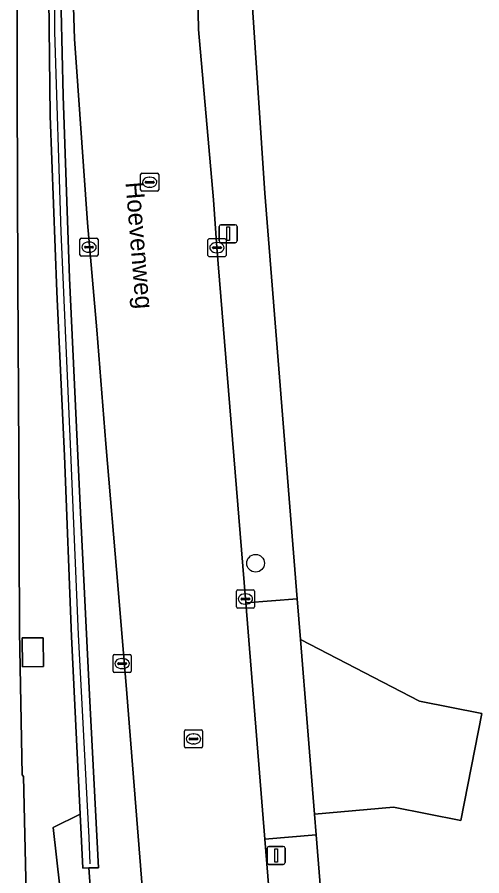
# Model space of a CAD drawing. Extents: x 157692 to 159674, y 381452 to 383291.
# Drawn here: x 157862.74 to 157888.49, y 382049.29 to 382096.87 of the extents above; entities that cross this region are included whole.
import ezdxf

# ---------------------------------------------------------------- set-up
doc = ezdxf.new("R2010")
doc.units = 0
for name, color, linetype in [('IMGEO_Berm_groen', 7, 'Continuous'), ('IMGEO_Boom', 7, 'Continuous'), ('IMGEO_Damwand', 7, 'Continuous'), ('IMGEO_Erf', 7, 'Continuous'), ('IMGEO_Grasland_overig', 7, 'Continuous'), ('IMGEO_Kolk', 7, 'Continuous'), ('IMGEO_Lichtmast', 7, 'Continuous'), ('IMGEO_Muur', 7, 'Continuous'), ('IMGEO_Openbare_ruimte_label', 7, 'Continuous'), ('IMGEO_Rijbaan_autoweg', 7, 'Continuous'), ('IMGEO_Rijbaan_lokaal_open', 7, 'Continuous'), ('IMGEO_Rioolput', 7, 'Continuous'), ('IMGEO_Terreindeel_gesloten', 7, 'Continuous'), ('IMGEO_Voetpad_open', 7, 'Continuous')]:
    doc.layers.add(name, color=color, linetype=linetype)

msp = doc.modelspace()

# ---------------------------------------------------------------- linework, layer by layer
at = {"layer": 'IMGEO_Berm_groen'}
for points in [[(157865.425, 382160.91), (157865.05, 382154.363), (157864.474, 382147.952), (157864.058, 382142.231), (157865.186, 382142.176), (157865.108, 382140.578), (157863.948, 382140.634), (157863.712, 382136.719), (157863.198, 382126.221), (157862.886, 382118.229), (157862.796, 382114.688), (157862.791, 382104.04), (157862.748, 382099.529), (157862.74, 382092.835), (157862.768, 382082.253), (157862.839, 382072.603), (157862.865, 382062.831), (157863.011, 382054.891), (157863.082, 382054.797), (157863.405, 382041.04)], [(157871.576, 382023.267), (157870.986, 382031.847), (157870.47, 382038.411), (157869.622, 382049.165), (157868.821, 382059.387), (157868.329, 382065.166), (157867.661, 382073.221), (157867.158, 382079.552), (157866.641, 382085.477), (157866.108, 382093.059), (157865.914, 382095.666), (157865.775, 382100.358), (157865.866, 382105.246), (157866.047, 382108.426), (157866.439, 382112.482), (157867.045, 382117.03), (157868.022, 382122.573), (157869.408, 382129.429), (157871.426, 382139.303), (157873.582, 382149.701), (157875.281, 382157.955)], [(157865.646, 382043.907), (157864.736, 382051.955), (157866.226, 382052.703), (157866.025, 382056.837), (157865.759, 382062.558), (157865.364, 382072.554), (157864.934, 382081.648), (157864.564, 382091.402), (157864.451, 382101.2)], [(157865.118, 382099.619), (157865.298, 382092.516), (157865.645, 382082.41), (157866.252, 382069.426), (157866.745, 382059.319), (157867.247, 382049.73), (157866.717, 382049.722), (157868.723, 382022.023)]]:
    msp.add_lwpolyline(points, dxfattribs=at)
msp.add_lwpolyline([(157864.198, 382060.884), (157863.037, 382060.866), (157863.024, 382062.466), (157864.175, 382062.483)], close=True, dxfattribs=at)
at = {"layer": 'IMGEO_Boom'}
msp.add_circle((157875.955, 382066.608), 0.489, dxfattribs=at)
at = {"layer": 'IMGEO_Damwand'}
msp.add_lwpolyline([(157866.597, 382130.428), (157865.692, 382121.331), (157865.099, 382113.024), (157864.8, 382104.625), (157864.807, 382096.063), (157865.159, 382084.979), (157865.683, 382073.208), (157866.12, 382062.663), (157866.714, 382051.403), (157866.776, 382049.942)], dxfattribs=at)
at = {"layer": 'IMGEO_Erf'}
msp.add_lwpolyline([(157875.768, 382105.479), (157875.755, 382097.986), (157876.464, 382087.116), (157878.268, 382064.633), (157878.448, 382062.387), (157885.047, 382058.968), (157888.494, 382058.282), (157887.326, 382052.352), (157883.605, 382053.086), (157879.225, 382052.703), (157879.317, 382051.562), (157880.959, 382031.099), (157882.495, 382012.836), (157884.473, 381992.148), (157885.166, 381980.124), (157887.103, 381956.606)], dxfattribs=at)
at = {"layer": 'IMGEO_Grasland_overig'}
msp.add_lwpolyline([(157868.723, 382022.023), (157866.717, 382049.722), (157866.375, 382049.713), (157866.226, 382052.703), (157864.736, 382051.955), (157865.646, 382043.907), (157866.36, 382035.462), (157867.189, 382028.083), (157867.916, 382023.142)], close=True, dxfattribs=at)
at = {"layer": 'IMGEO_Kolk'}
for p, q in [((157866.221, 382083.697), (157866.221, 382084.549)), ((157866.296, 382084.623), (157867.148, 382084.623)), ((157867.222, 382084.549), (157867.222, 382083.697)), ((157873.314, 382083.671), (157873.314, 382084.523)), ((157873.389, 382084.597), (157874.241, 382084.597)), ((157874.315, 382084.523), (157874.315, 382083.671)), ((157866.48, 382084.117), (157866.48, 382084.129)), ((157866.918, 382084.08), (157866.52, 382084.08)), ((157866.523, 382084.166), (157866.921, 382084.166)), ((157866.709, 382084.403), (157866.734, 382084.403)), ((157866.964, 382084.129), (157866.964, 382084.117)), ((157873.573, 382084.091), (157873.573, 382084.103)), ((157874.011, 382084.054), (157873.613, 382084.054)), ((157873.616, 382084.14), (157874.014, 382084.14)), ((157873.802, 382084.377), (157873.827, 382084.377)), ((157874.057, 382084.103), (157874.057, 382084.091)), ((157867.148, 382083.623), (157866.296, 382083.623)), ((157866.732, 382083.843), (157866.707, 382083.843)), ((157874.241, 382083.597), (157873.389, 382083.597)), ((157873.825, 382083.817), (157873.8, 382083.817)), ((157874.888, 382064.201), (157874.888, 382065.053)), ((157874.963, 382065.127), (157875.815, 382065.127)), ((157875.889, 382065.053), (157875.889, 382064.201)), ((157875.147, 382064.621), (157875.147, 382064.633)), ((157875.585, 382064.584), (157875.187, 382064.584)), ((157875.19, 382064.67), (157875.588, 382064.67)), ((157875.376, 382064.907), (157875.401, 382064.907)), ((157875.631, 382064.633), (157875.631, 382064.621)), ((157875.815, 382064.127), (157874.963, 382064.127)), ((157875.399, 382064.347), (157875.374, 382064.347)), ((157868.057, 382060.621), (157868.057, 382061.473)), ((157868.132, 382061.547), (157868.984, 382061.547)), ((157868.545, 382061.327), (157868.57, 382061.327)), ((157869.058, 382061.473), (157869.058, 382060.621)), ((157868.316, 382061.041), (157868.316, 382061.053)), ((157868.754, 382061.004), (157868.356, 382061.004)), ((157868.359, 382061.09), (157868.757, 382061.09)), ((157868.568, 382060.767), (157868.543, 382060.767)), ((157868.8, 382061.053), (157868.8, 382061.041)), ((157868.984, 382060.547), (157868.132, 382060.547))]:
    msp.add_line(p, q, dxfattribs=at)
for points in [[(157866.221, 382083.697), (157866.221, 382084.549)], [(157866.296, 382084.623), (157867.148, 382084.623)], [(157867.222, 382084.549), (157867.222, 382083.697)], [(157873.314, 382083.671), (157873.314, 382084.523)], [(157873.389, 382084.597), (157874.241, 382084.597)], [(157874.315, 382084.523), (157874.315, 382083.671)], [(157867.148, 382083.623), (157866.296, 382083.623)], [(157874.241, 382083.597), (157873.389, 382083.597)], [(157874.888, 382064.201), (157874.888, 382065.053)], [(157874.963, 382065.127), (157875.815, 382065.127)], [(157875.889, 382065.053), (157875.889, 382064.201)], [(157875.815, 382064.127), (157874.963, 382064.127)], [(157868.057, 382060.621), (157868.057, 382061.473)], [(157868.132, 382061.547), (157868.984, 382061.547)], [(157869.058, 382061.473), (157869.058, 382060.621)], [(157868.984, 382060.547), (157868.132, 382060.547)]]:
    msp.add_lwpolyline(points, dxfattribs=at)
for centre, radius, start, end in [((157866.298, 382084.547), 0.0765, 91.552, 178.448), ((157866.298, 382084.547), 0.0765, 91.552, 178.448), ((157867.146, 382084.547), 0.0765, 1.552, 88.448), ((157867.146, 382084.547), 0.0765, 1.552, 88.448), ((157873.391, 382084.521), 0.0765, 91.552, 178.448), ((157873.391, 382084.521), 0.0765, 91.552, 178.448), ((157874.239, 382084.521), 0.0765, 1.552, 88.448), ((157874.239, 382084.521), 0.0765, 1.552, 88.448), ((157866.52, 382084.126), 0.0403, 85.8775, 175.7526), ((157866.517, 382084.116), 0.0366, 178.938, 274.7102), ((157866.921, 382084.123), 0.043, 264.8664, 352.4533), ((157866.925, 382084.128), 0.0386, 1.7309, 96.639), ((157873.613, 382084.1), 0.0403, 85.8775, 175.7526), ((157873.61, 382084.09), 0.0366, 178.938, 274.7102), ((157874.014, 382084.097), 0.043, 264.8664, 352.4533), ((157874.018, 382084.102), 0.0386, 1.7309, 96.639), ((157866.298, 382083.699), 0.0765, 181.552, 268.448), ((157866.298, 382083.699), 0.0765, 181.552, 268.448), ((157867.146, 382083.699), 0.0765, 271.552, 358.448), ((157867.146, 382083.699), 0.0765, 271.552, 358.448), ((157873.391, 382083.673), 0.0765, 181.552, 268.448), ((157873.391, 382083.673), 0.0765, 181.552, 268.448), ((157874.239, 382083.673), 0.0765, 271.552, 358.448), ((157874.239, 382083.673), 0.0765, 271.552, 358.448), ((157874.965, 382065.051), 0.0765, 91.552, 178.448), ((157874.965, 382065.051), 0.0765, 91.552, 178.448), ((157875.813, 382065.051), 0.0765, 1.552, 88.448), ((157875.813, 382065.051), 0.0765, 1.552, 88.448), ((157875.187, 382064.63), 0.0403, 85.8775, 175.7526), ((157875.184, 382064.62), 0.0366, 178.938, 274.7102), ((157875.588, 382064.627), 0.043, 264.8664, 352.4533), ((157875.592, 382064.632), 0.0386, 1.7309, 96.639), ((157874.965, 382064.203), 0.0765, 181.552, 268.448), ((157874.965, 382064.203), 0.0765, 181.552, 268.448), ((157875.813, 382064.203), 0.0765, 271.552, 358.448), ((157875.813, 382064.203), 0.0765, 271.552, 358.448), ((157868.134, 382061.471), 0.0765, 91.552, 178.448), ((157868.134, 382061.471), 0.0765, 91.552, 178.448), ((157868.982, 382061.471), 0.0765, 1.552, 88.448), ((157868.982, 382061.471), 0.0765, 1.552, 88.448), ((157868.356, 382061.05), 0.0403, 85.8775, 175.7526), ((157868.353, 382061.04), 0.0366, 178.938, 274.7102), ((157868.757, 382061.047), 0.043, 264.8664, 352.4533), ((157868.761, 382061.052), 0.0386, 1.7309, 96.639), ((157868.134, 382060.623), 0.0765, 181.552, 268.448), ((157868.134, 382060.623), 0.0765, 181.552, 268.448), ((157868.982, 382060.623), 0.0765, 271.552, 358.448), ((157868.982, 382060.623), 0.0765, 271.552, 358.448)]:
    msp.add_arc(centre, radius, start, end, dxfattribs=at)
for centre, major_axis, ratio, start_param, end_param in [((157866.708, 382084.123), (-0.387, 0.002), 0.722429, 4.712389, 7.853982), ((157866.733, 382084.123), (-0.39, 0.002), 0.717154, 1.570796, 4.712389), ((157873.801, 382084.097), (-0.387, 0.002), 0.722429, 4.712389, 7.853982), ((157873.826, 382084.097), (-0.39, 0.002), 0.717154, 1.570796, 4.712389), ((157875.375, 382064.627), (-0.387, 0.002), 0.722429, 4.712389, 7.853982), ((157875.4, 382064.627), (-0.39, 0.002), 0.717154, 1.570796, 4.712389), ((157868.544, 382061.047), (-0.387, 0.002), 0.722429, 4.712389, 7.853982), ((157868.569, 382061.047), (-0.39, 0.002), 0.717154, 1.570796, 4.712389)]:
    msp.add_ellipse(centre, major_axis=major_axis, ratio=ratio, start_param=start_param, end_param=end_param, dxfattribs=at)
at = {"layer": 'IMGEO_Lichtmast'}
for p, q in [((157873.937, 382084.468), (157873.937, 382085.268)), ((157873.937, 382085.268), (157873.937, 382084.468)), ((157874.037, 382085.368), (157874.827, 382085.368)), ((157874.827, 382085.368), (157874.037, 382085.368)), ((157874.927, 382085.268), (157874.927, 382084.468)), ((157874.927, 382084.468), (157874.927, 382085.268)), ((157874.827, 382084.368), (157874.037, 382084.368)), ((157874.037, 382084.368), (157874.827, 382084.368)), ((157876.595, 382050.016), (157876.595, 382050.816)), ((157876.595, 382050.816), (157876.595, 382050.016)), ((157876.695, 382050.916), (157877.485, 382050.916)), ((157877.485, 382050.916), (157876.695, 382050.916)), ((157877.585, 382050.816), (157877.585, 382050.016)), ((157877.585, 382050.016), (157877.585, 382050.816)), ((157877.485, 382049.916), (157876.695, 382049.916)), ((157876.695, 382049.916), (157877.485, 382049.916))]:
    msp.add_line(p, q, dxfattribs=at)
for points in [[(157874.357, 382085.243), (157874.507, 382085.243), (157874.507, 382084.493), (157874.357, 382084.493), (157874.357, 382085.243)], [(157877.015, 382050.791), (157877.165, 382050.791), (157877.165, 382050.041), (157877.015, 382050.041), (157877.015, 382050.791)]]:
    msp.add_lwpolyline(points, dxfattribs=at)
for centre, start, end in [((157874.037, 382085.268), 90, 180), ((157874.037, 382085.268), 90, 180), ((157874.827, 382085.268), 0, 90), ((157874.827, 382085.268), 360, 90), ((157874.037, 382084.468), 180, 270), ((157874.037, 382084.468), 180, 270), ((157874.827, 382084.468), 270, 0), ((157874.827, 382084.468), 270, 0), ((157876.695, 382050.816), 90, 180), ((157876.695, 382050.816), 90, 180), ((157877.485, 382050.816), 0, 90), ((157877.485, 382050.816), 360, 90), ((157876.695, 382050.016), 180, 270), ((157876.695, 382050.016), 180, 270), ((157877.485, 382050.016), 270, 0), ((157877.485, 382050.016), 270, 0)]:
    msp.add_arc(centre, 0.1, start, end, dxfattribs=at)
at = {"layer": 'IMGEO_Muur'}
msp.add_lwpolyline([(157864.451, 382101.2), (157864.564, 382091.402), (157864.934, 382081.648), (157865.364, 382072.554), (157865.759, 382062.558), (157866.025, 382056.837), (157866.226, 382052.703), (157866.375, 382049.713), (157866.717, 382049.722), (157867.247, 382049.73), (157866.745, 382059.319), (157866.252, 382069.426), (157865.645, 382082.41), (157865.298, 382092.516), (157865.118, 382099.619)], dxfattribs=at)
at = {"layer": 'IMGEO_Rijbaan_autoweg'}
msp.add_lwpolyline([(157863.405, 382041.04), (157863.082, 382054.797), (157863.011, 382054.891), (157862.865, 382062.831), (157862.839, 382072.603), (157862.768, 382082.253), (157862.74, 382092.835), (157862.748, 382099.529), (157862.791, 382104.04), (157862.796, 382114.688), (157862.886, 382118.229), (157863.198, 382126.221), (157863.712, 382136.719), (157863.948, 382140.634), (157864.058, 382142.231), (157864.474, 382147.952), (157865.05, 382154.363), (157865.425, 382160.91)], dxfattribs=at)
at = {"layer": 'IMGEO_Rijbaan_lokaal_open'}
for points in [[(157876.98, 382166.191), (157875.281, 382157.955), (157873.582, 382149.701), (157871.426, 382139.303), (157869.408, 382129.429), (157868.022, 382122.573), (157867.045, 382117.03), (157866.439, 382112.482), (157866.047, 382108.426), (157865.866, 382105.246), (157865.775, 382100.358), (157865.914, 382095.666), (157866.108, 382093.059), (157866.641, 382085.477), (157867.158, 382079.552), (157867.661, 382073.221), (157868.329, 382065.166), (157868.821, 382059.387), (157869.622, 382049.165), (157870.47, 382038.411), (157870.986, 382031.847), (157871.576, 382023.267), (157877.712, 381946.227)], [(157877.38, 382040.147), (157876.471, 382051.324), (157875.406, 382064.42), (157875.389, 382064.627), (157873.815, 382084.097), (157873.613, 382086.739), (157872.794, 382096.181), (157872.707, 382100.949), (157872.785, 382104.713), (157873.026, 382108.688), (157874.175, 382117.687), (157874.961, 382122.317), (157876.358, 382128.915), (157878.215, 382137.998), (157881.073, 382151.961), (157883.035, 382160.885), (157884.009, 382165.611)]]:
    msp.add_lwpolyline(points, dxfattribs=at)
msp.add_lwpolyline([(157878.448, 382062.387), (157879.225, 382052.703), (157883.605, 382053.086), (157887.326, 382052.352), (157888.494, 382058.282), (157885.047, 382058.968)], close=True, dxfattribs=at)
at = {"layer": 'IMGEO_Rioolput'}
for p, q in [((157869.583, 382087.296), (157869.583, 382088.148)), ((157869.658, 382088.222), (157870.51, 382088.222)), ((157870.071, 382088.002), (157870.096, 382088.002)), ((157870.584, 382088.148), (157870.584, 382087.296)), ((157869.842, 382087.716), (157869.842, 382087.728)), ((157870.28, 382087.679), (157869.882, 382087.679)), ((157869.885, 382087.765), (157870.283, 382087.765)), ((157870.094, 382087.442), (157870.069, 382087.442)), ((157870.326, 382087.728), (157870.326, 382087.716)), ((157870.51, 382087.222), (157869.658, 382087.222)), ((157872.015, 382056.446), (157872.015, 382057.298)), ((157872.09, 382057.372), (157872.942, 382057.372)), ((157872.503, 382057.152), (157872.528, 382057.152)), ((157873.016, 382057.298), (157873.016, 382056.446)), ((157872.274, 382056.866), (157872.274, 382056.878)), ((157872.712, 382056.829), (157872.314, 382056.829)), ((157872.317, 382056.915), (157872.715, 382056.915)), ((157872.526, 382056.592), (157872.501, 382056.592)), ((157872.758, 382056.878), (157872.758, 382056.866)), ((157872.942, 382056.372), (157872.09, 382056.372))]:
    msp.add_line(p, q, dxfattribs=at)
for points in [[(157869.583, 382087.296), (157869.583, 382088.148)], [(157869.658, 382088.222), (157870.51, 382088.222)], [(157870.584, 382088.148), (157870.584, 382087.296)], [(157870.51, 382087.222), (157869.658, 382087.222)], [(157872.015, 382056.446), (157872.015, 382057.298)], [(157872.09, 382057.372), (157872.942, 382057.372)], [(157873.016, 382057.298), (157873.016, 382056.446)], [(157872.942, 382056.372), (157872.09, 382056.372)]]:
    msp.add_lwpolyline(points, dxfattribs=at)
for centre, radius, start, end in [((157869.66, 382088.146), 0.0765, 91.552, 178.448), ((157869.66, 382088.146), 0.0765, 91.552, 178.448), ((157870.508, 382088.146), 0.0765, 1.552, 88.448), ((157870.508, 382088.146), 0.0765, 1.552, 88.448), ((157869.882, 382087.725), 0.0403, 85.8775, 175.7526), ((157869.879, 382087.715), 0.0366, 178.938, 274.7102), ((157870.283, 382087.722), 0.043, 264.8664, 352.4533), ((157870.287, 382087.727), 0.0386, 1.7309, 96.639), ((157869.66, 382087.298), 0.0765, 181.552, 268.448), ((157869.66, 382087.298), 0.0765, 181.552, 268.448), ((157870.508, 382087.298), 0.0765, 271.552, 358.448), ((157870.508, 382087.298), 0.0765, 271.552, 358.448), ((157872.092, 382057.296), 0.0765, 91.552, 178.448), ((157872.092, 382057.296), 0.0765, 91.552, 178.448), ((157872.94, 382057.296), 0.0765, 1.552, 88.448), ((157872.94, 382057.296), 0.0765, 1.552, 88.448), ((157872.314, 382056.875), 0.0403, 85.8775, 175.7526), ((157872.311, 382056.865), 0.0366, 178.938, 274.7102), ((157872.715, 382056.872), 0.043, 264.8664, 352.4533), ((157872.719, 382056.877), 0.0386, 1.7309, 96.639), ((157872.092, 382056.448), 0.0765, 181.552, 268.448), ((157872.092, 382056.448), 0.0765, 181.552, 268.448), ((157872.94, 382056.448), 0.0765, 271.552, 358.448), ((157872.94, 382056.448), 0.0765, 271.552, 358.448)]:
    msp.add_arc(centre, radius, start, end, dxfattribs=at)
for centre, major_axis, ratio, start_param, end_param in [((157870.07, 382087.722), (-0.387, 0.002), 0.722429, 4.712389, 7.853982), ((157870.095, 382087.722), (-0.39, 0.002), 0.717154, 1.570796, 4.712389), ((157872.502, 382056.872), (-0.387, 0.002), 0.722429, 4.712389, 7.853982), ((157872.527, 382056.872), (-0.39, 0.002), 0.717154, 1.570796, 4.712389)]:
    msp.add_ellipse(centre, major_axis=major_axis, ratio=ratio, start_param=start_param, end_param=end_param, dxfattribs=at)
at = {"layer": 'IMGEO_Terreindeel_gesloten'}
msp.add_lwpolyline([(157864.198, 382060.884), (157864.175, 382062.483), (157863.024, 382062.466), (157863.037, 382060.866)], close=True, dxfattribs=at)
at = {"layer": 'IMGEO_Voetpad_open'}
msp.add_lwpolyline([(157876.815, 382115.562), (157877.485, 382118.829), (157879.248, 382127.289), (157879.468, 382128.344), (157876.358, 382128.915), (157874.961, 382122.317), (157874.175, 382117.687), (157873.026, 382108.688), (157872.785, 382104.713), (157872.707, 382100.949), (157872.794, 382096.181), (157873.613, 382086.739), (157873.815, 382084.097), (157875.389, 382064.627), (157875.406, 382064.42), (157878.268, 382064.633), (157876.464, 382087.116), (157875.755, 382097.986)], dxfattribs=at)
for points in [[(157878.448, 382062.387), (157878.268, 382064.633), (157875.406, 382064.42), (157876.471, 382051.324), (157879.317, 382051.562), (157879.225, 382052.703)], [(157880.959, 382031.099), (157879.317, 382051.562), (157876.471, 382051.324), (157877.38, 382040.147), (157878.096, 382030.891), (157879.093, 382016.501), (157879.267, 382014.333), (157880.461, 382000.889), (157880.48, 382000.654), (157881.168, 381991.916), (157884.473, 381992.148), (157882.495, 382012.836)]]:
    msp.add_lwpolyline(points, close=True, dxfattribs=at)

# ---------------------------------------------------------------- texts
at = {"layer": 'IMGEO_Openbare_ruimte_label'}
msp.add_text('Hoevenweg', height=1, rotation=274.5876, dxfattribs=at).set_placement((157868.746, 382087.708))

doc.saveas('drawing.dxf')
